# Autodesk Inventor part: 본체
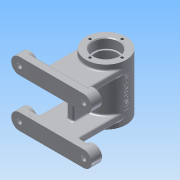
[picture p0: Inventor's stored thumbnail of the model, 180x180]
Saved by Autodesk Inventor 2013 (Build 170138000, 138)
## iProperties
Created: 2015-11
Part Number: 본체
Material: 알루미늄 6061
Document SubType Name: Modeling
Designer: Administrator
Density: 2.71 g/cm^3
Mass: 359.017 g
Surface Area: 459.644 cm^2
Volume: 132.479 cm^3
Author: Administrator
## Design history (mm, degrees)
sketch "스케치1"
  geometry: L1 (-40, 40)-(40, 40); L2 (40, 20)-(-40, 20); L3 (-40, -40)-(40, -40); L4 (40, -20)-(-40, -20); A1 r 10 centre (-40, 30) between (-40, 40) and (-40, 20); A2 r 10 centre (40, 30) between (40, 20) and (40, 40); A3 r 10 centre (-40, -30) between (-40, -20) and (-40, -40); A4 r 10 centre (40, -30) between (40, -40) and (40, -20); 1 further point
  constraints: 8 end point, 8 point on circle, 4 centre point, 3 tangent, 1 parallel
extrude "돌출1" new body sketch "스케치1" distance "d6" = 10; taper "d7" = 0 deg
sketch "스케치2"
  geometry: C1 r 10 at (-40, 30); C2 r 10 at (40, 30); A1 r 10 centre (-40, 30) between (-40, 40) and (-40, 20) reference; A2 r 10 centre (40, 30) between (40, 20) and (40, 40) reference; 1 further point
  constraints: 2 centre point, 2 coincident
  dimensions: "d8" = 20 diameter of C1; "d9" = 20 diameter of C2
extrude "돌출2" join sketch "스케치2" distance "d10" = 3; taper "d11" = 0 deg
sketch "스케치3"
  geometry: C1 r 10 at (-40, -30); C2 r 10 at (40, -30); A1 r 10 centre (40, -30) between (40, -40) and (40, -20) reference; A2 r 10 centre (-40, -30) between (-40, -20) and (-40, -40) reference; 1 further point
  constraints: 2 centre point, 2 coincident
  dimensions: "d12" = 20 diameter of C1; "d13" = 20 diameter of C2
extrude "돌출3" join sketch "스케치3" distance "d14" = 3; taper "d15" = 0 deg
sketch "스케치4"
  geometry: L1 (0, 0)-(0, 68); C1 r 25 at (0, 68)
  constraints: 2 end point, 1 centre point, 1 coincident, 1 vertical
  dimensions: "d16" = 68 distance of L1.start L1.end; "d17" = 50 diameter of C1
extrude "돌출4" join sketch "스케치4" stored distance "d18" = 70; taper "d19" = 0 deg
sketch "스케치5"
  geometry: L1 (0, 10)-(80, 10) reference; L2 (65, 68)-(65, 10); L3 (65, 10)-(15, 10); L4 (15, 10)-(15, 68); L5 (15, 68)-(65, 68); 1 further point
  constraints: 8 end point, 3 perpendicular, 2 point on line
extrude "돌출5" join sketch "스케치5" distance "d23" = 8; taper "d24" = 0 deg
sketch "스케치6"
  geometry: L1 (0, 10)-(80, 10) reference; L2 (65, 68)-(65, 10); L3 (65, 10)-(15, 10); L4 (15, 10)-(15, 68); L5 (15, 68)-(65, 68); 1 further point
  constraints: 8 end point, 3 perpendicular, 2 point on line
extrude "돌출6" join sketch "스케치6" distance "d28" = 8; taper "d29" = 0 deg
sketch "스케치7"
  geometry: L1 (0, 0)-(33, 0); L2 (33, -20)-(23, -20); L3 (23, -20)-(23, 20); L4 (23, -20)-(53, -20); L5 (53, -20)-(53, 20); L6 (53, 20)-(23, 20)
  constraints: 12 end point, 2 perpendicular, 1 horizontal, 1 parallel
extrude "돌출7" join sketch "스케치7" stored distance "d40" = 8; taper "d41" = 0 deg
hole "구멍1" diameter "d44" = 6; stored, may be unused: countersink angle "d48" = 90 deg, drill point angle "d50" = 118 deg; dims "d42" = 10, "d43" = 10, "d45" = 6, "d46" = 12, "d47" = 4, "d49" = 13
hole "구멍2" diameter "d53" = 6; stored, may be unused: countersink angle "d57" = 90 deg, drill point angle "d59" = 118 deg; dims "d51" = 10, "d52" = 10, "d54" = 6, "d55" = 12, "d56" = 4, "d58" = 13
hole "구멍3" diameter "d62" = 6; stored, may be unused: countersink angle "d66" = 90 deg, drill point angle "d68" = 118 deg; dims "d60" = 10, "d61" = 10, "d63" = 6, "d64" = 12, "d65" = 4, "d67" = 13
hole "구멍4" diameter "d71" = 6; stored, may be unused: countersink angle "d75" = 90 deg, drill point angle "d77" = 118 deg; dims "d69" = 10, "d70" = 10, "d72" = 6, "d73" = 12, "d74" = 4, "d76" = 13
chamfer "모따기1" distance "d78" = 1; stored, may be unused: second distance "d79" = 2, angle "d80" = 45 deg
chamfer "모따기2" distance "d81" = 1; stored, may be unused: second distance "d82" = 2, angle "d83" = 45 deg
chamfer "모따기3" distance "d84" = 1; stored, may be unused: second distance "d85" = 2, angle "d86" = 45 deg
chamfer "모따기4" distance "d87" = 1; stored, may be unused: second distance "d88" = 2, angle "d89" = 45 deg
node "작업 평면2"
sketch "스케치8"
  geometry: C1 r 5 at (0, 0); 1 further point
  constraints: 1 centre point, 1 coincident
  dimensions: "d91" = 10 diameter of C1
extrude "돌출8" join sketch "스케치8" stored distance "d92" = 8; taper "d93" = 0 deg
sketch "스케치9"
  geometry: C1 r 25 at (0, 0) reference; C2 r 16 at (0, 0); 1 further point
  constraints: 1 centre point, 1 coincident
  dimensions: "d94" = 32 diameter of C2
extrude "돌출9" cut sketch "스케치9" distance "d95" = 12; taper "d96" = 0 deg
sketch "스케치10"
  geometry: C1 r 16 at (0, 0) reference; C2 r 14 at (0, 0); 1 further point
  constraints: 1 centre point, 1 coincident
  dimensions: "d97" = 28 diameter of C2
extrude "돌출10" cut sketch "스케치10" distance "d98" = 2; taper "d99" = 0 deg
sketch "스케치11"
  geometry: C1 r 25 at (0, 0) reference; C2 r 16 at (0, 0); 1 further point
  constraints: 1 centre point, 1 coincident
  dimensions: "d100" = 32 diameter of C2
extrude "돌출11" cut sketch "스케치11" distance "d101" = 12; taper "d102" = 0 deg
sketch "스케치12"
  geometry: C1 r 16 at (0, 0) reference; C2 r 14 at (0, 0); 1 further point
  constraints: 1 centre point, 1 coincident
  dimensions: "d103" = 28 diameter of C2
extrude "돌출12" cut sketch "스케치12" distance "d104" = 2; taper "d105" = 0 deg
sketch "스케치13"
  geometry: C1 r 21 at (0, 0); 1 further point
  constraints: 1 centre point
  dimensions: "d106" = 42 diameter of C1
extrude "돌출13" cut sketch "스케치13" distance "d107" = 42; taper "d108" = 0 deg
hole "구멍5" diameter "d111" = 5.188; stored, may be unused: countersink angle "d115" = 90 deg, drill point angle "d117" = 0 deg; dims "d112" = 6, "d113" = 12, "d114" = 4, "d116" = 13, "d206" = 10, "d207" = 10
sketch "스케치14"
  geometry: C1 r 25 at (0, 0) reference; A1 r 20 centre (0, 0) between (0, 20) and (-20, 0); 3 further points
  constraints: 4 point on circle, 1 centre point, 1 coincident
  dimensions: "d118" = 40 diameter of A1
hole "구멍6" sketch "스케치14" at (0, 20), (-20, 0), (20, 0), (0, -20) diameter "d119" = 3.242; stored, may be unused: countersink angle "d123" = 90 deg, drill point angle "d125" = 118 deg; dims "d120" = 8, "d121" = 12, "d122" = 4, "d124" = 10
sketch "스케치15"
  geometry: C1 r 25 at (0, 0) reference; A1 r 20 centre (0, 0) between (0, 20) and (20, 0); 3 further points
  constraints: 4 point on circle, 1 centre point, 1 coincident
  dimensions: "d126" = 40 diameter of A1
hole "구멍7" sketch "스케치15" at (0, 20), (20, 0), (0, -20), (-20, 0) diameter "d127" = 3.242; stored, may be unused: countersink angle "d131" = 90 deg, drill point angle "d133" = 118 deg; dims "d128" = 8, "d129" = 12, "d130" = 4, "d132" = 10
sketch "스케치16"
  geometry: L1 (0, 0)-(0, 68); L2 (0, 68)-(14, 43.751)
  constraints: 4 end point, 1 vertical
  dimensions: "d134" = 68 distance of L1.start L1.end; "d136" = 28 distance of L1.end L2.end; "d137" = 30 deg angle of L2 L1
node "작업 평면3"
sketch "스케치18"
  geometry: L1 (8, 29.5)-(-8, 29.5); L2 (-8, 36.5)-(8, 36.5); A1 r 3.5 centre (8, 33) between (8, 29.5) and (8, 36.5); A2 r 3.5 centre (-8, 33) between (-8, 36.5) and (-8, 29.5); 1 further point
  constraints: 4 end point, 4 point on circle, 2 centre point, 2 tangent
extrude "돌출15" cut sketch "스케치18" stored distance "d157" = 42; taper "d158" = 0 deg
sketch "스케치21"
  geometry: L1 (0, 0)-(0, 68); L2 (0, 68)-(-14, 43.751)
  constraints: 4 end point, 1 vertical
  dimensions: "d173" = 68 distance of L1.start L1.end; "d176" = 28 distance of L1.end L2.end
node "작업 평면6"
sketch "스케치22"
  geometry: C1 r 6 at (0, 0); 1 further point
  constraints: 1 centre point
  dimensions: "d177" = 12 diameter of C1
extrude "돌출16" join sketch "스케치22" stored distance "d178" = 42; taper "d179" = 0 deg
hole "구멍9" diameter "d182" = 5.188; stored, may be unused: countersink angle "d186" = 90 deg, drill point angle "d188" = 0 deg; dims "d183" = 8, "d184" = 12, "d185" = 4, "d187" = 10, "d208" = 10, "d209" = 10
node "작업 평면7"
sketch "스케치23"
  geometry: L1 (68, -35)-(68, 35); L2 (93, 35)-(43, 35) reference; L3 (93, 0)-(43, 0); 2 further points
  constraints: 4 end point, 1 parallel, 1 other
  dimensions: "d191" = 35 distance between parallel lines of L2 L3
feature "엠보싱2" sketch "스케치23" dims "d192" = 0.5, "d193" = 0
fillet "모깎기3" dims "d194" = 2, "d197" = 2, "d198" = 0.3, "d199" = 3
chamfer "모따기5" distance "d200" = 1; stored, may be unused: second distance "d201" = 2, angle "d202" = 45 deg
chamfer "모따기6" distance "d203" = 1; stored, may be unused: second distance "d204" = 2, angle "d205" = 45 deg
node "솔리드1"
other parameters: "d90" = 96, "d189" = 25
